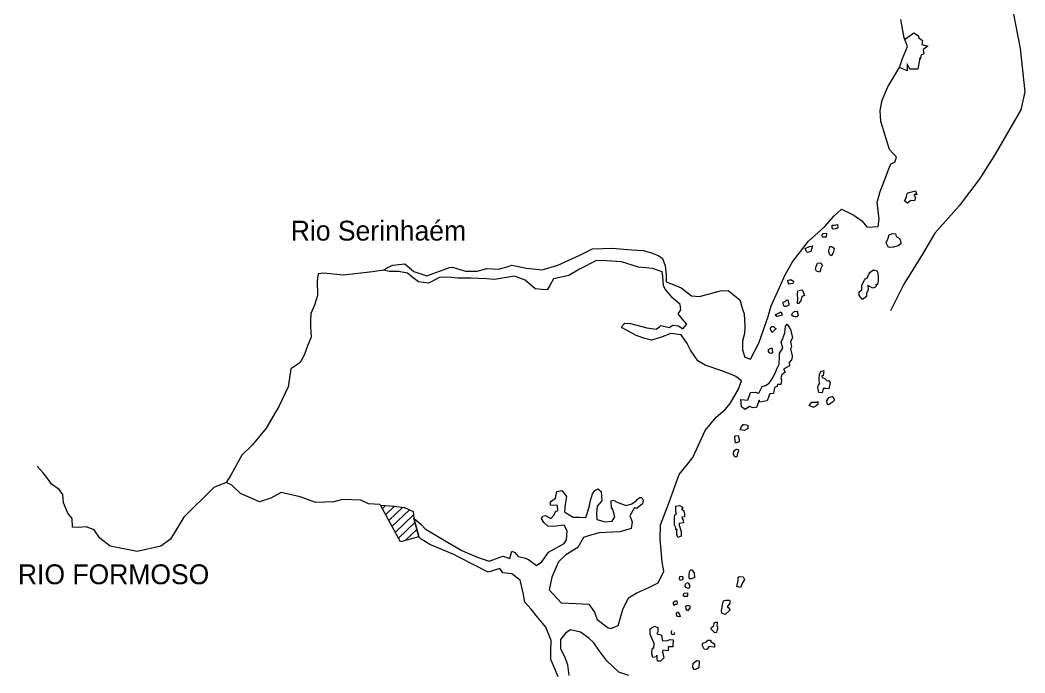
# Model space of a CAD drawing. Extents: x 662444 to 1640468, y 7452018 to 9606170.
# Drawn here: x 1574839 to 1609576, y 9023325 to 9045876 of the extents above; entities that cross this region are included whole.
import ezdxf

# ---------------------------------------------------------------- set-up
doc = ezdxf.new("R2010")
doc.units = 0
doc.layers.add('Level 1', color=7, linetype='Continuous')
doc.layers.add('Level 3', color=7, linetype='Continuous')

msp = doc.modelspace()

# ---------------------------------------------------------------- linework, layer by layer
at = {"layer": 'Level 1'}
for points in [[(1603524, 9039212), (1603667, 9039136), (1603937, 9038941), (1604118, 9038725), (1604506, 9038748), (1604537, 9038998), (1604463, 9039576), (1604578, 9039954), (1604752, 9040428), (1604847, 9040684), (1604943, 9040909), (1605074, 9040970), (1605134, 9041138), (1604899, 9041405), (1604592, 9042377), (1604577, 9042752), (1604644, 9043106), (1604834, 9043571), (1605222, 9044210), (1605239, 9044242), (1605344, 9044547), (1605517, 9044964), (1605403, 9045267), (1605290, 9045902)], [(1609180, 9046082), (1609417, 9044899), (1609576, 9043399), (1609436, 9042776), (1608544, 9041247), (1608020, 9040401), (1607300, 9039455), (1606467, 9038518), (1606041, 9037786), (1605392, 9036756), (1604931, 9035830)], [(1605403, 9045267), (1605450, 9045234), (1605739, 9045436), (1605898, 9045334), (1605896, 9045270), (1606031, 9045169), (1606012, 9045039), (1606220, 9044978), (1606055, 9044860), (1606084, 9044705), (1605995, 9044675), (1605958, 9044530), (1605943, 9044571), (1605877, 9044184), (1605602, 9044183), (1605509, 9044364), (1605503, 9044121), (1605239, 9044242)], [(1605564, 9039919), (1605662, 9039949), (1605792, 9039977), (1605837, 9039847), (1605749, 9039849), (1605748, 9039824), (1605794, 9039750), (1605759, 9039638), (1605629, 9039641), (1605514, 9039555), (1605411, 9039631), (1605487, 9039758), (1605490, 9039856), (1605523, 9039895), (1605564, 9039919)], [(1595750, 9035402), (1595936, 9035397), (1596506, 9035244), (1596829, 9035203), (1596944, 9035281), (1596994, 9035328), (1597283, 9035255), (1597406, 9035333), (1597599, 9035312), (1597751, 9035210), (1597884, 9035368), (1597727, 9035551), (1597586, 9035725), (1597678, 9035869), (1597659, 9036056), (1597399, 9036273), (1597155, 9036572), (1597086, 9036696), (1597054, 9037029), (1597041, 9037183), (1596697, 9037297), (1596213, 9037344), (1595635, 9037522), (1595126, 9037559), (1594763, 9037569), (1594173, 9037269), (1593804, 9037052), (1593284, 9036944), (1593148, 9036713), (1593055, 9036562), (1592885, 9036566), (1592643, 9036597), (1592296, 9036898), (1591927, 9037030), (1591245, 9036919), (1590963, 9036934), (1590422, 9036957), (1589976, 9036960), (1589630, 9036994), (1589339, 9036986), (1588962, 9036794), (1588607, 9036836), (1588433, 9036978), (1588235, 9037137), (1587921, 9037187), (1587598, 9037195), (1587397, 9037233), (1587545, 9037326), (1587725, 9037410), (1588138, 9037456), (1588455, 9037196), (1588896, 9037047), (1589688, 9037325), (1589784, 9037347), (1590234, 9037205), (1590646, 9037202), (1590980, 9037298), (1591375, 9037271), (1591709, 9037368), (1591840, 9037413), (1592347, 9037310), (1592887, 9037247), (1593424, 9037411), (1594194, 9037754), (1594628, 9037978), (1595316, 9038000), (1595977, 9037941), (1596389, 9037914), (1596702, 9037825), (1596926, 9037729), (1597046, 9037645), (1597144, 9037383), (1597176, 9037082), (1597170, 9036830), (1597530, 9036700), (1597698, 9036630), (1598048, 9036353), (1598330, 9036329), (1598753, 9036448), (1599054, 9036529), (1599321, 9036530), (1599718, 9036218), (1599814, 9035891), (1599875, 9035728), (1599896, 9035298), (1599881, 9035047), (1599818, 9034789), (1599810, 9034489), (1599892, 9034236), (1600085, 9034166), (1600382, 9034717), (1600706, 9035632), (1600804, 9036002), (1601095, 9036644), (1601284, 9037076), (1601539, 9037531), (1602099, 9038237), (1602645, 9038734), (1602979, 9039113), (1603236, 9039350), (1603524, 9039212)], [(1602721, 9038513), (1602709, 9038375), (1602645, 9038377), (1602580, 9038378), (1602565, 9038444), (1602599, 9038499), (1602721, 9038513)], [(1602986, 9038789), (1603092, 9038811), (1603114, 9038705), (1603048, 9038666), (1602950, 9038652), (1602911, 9038702), (1602913, 9038758), (1602914, 9038791), (1602978, 9038789)], [(1605021, 9038028), (1604899, 9038023), (1604844, 9038041), (1604783, 9038180), (1604852, 9038341), (1604887, 9038454), (1604985, 9038499), (1605099, 9038496), (1605129, 9038406), (1605224, 9038339), (1605278, 9038264), (1605284, 9038150), (1605193, 9038080), (1605021, 9038028)], [(1602135, 9038058), (1602232, 9038080), (1602170, 9037887), (1602064, 9037850), (1602025, 9037883), (1601980, 9037981), (1602135, 9038058)], [(1602963, 9037865), (1602887, 9037737), (1602831, 9037763), (1602793, 9037862), (1602795, 9037918), (1602831, 9038055), (1602894, 9038054), (1602982, 9038003), (1602963, 9037865)], [(1602571, 9037382), (1602519, 9037293), (1602491, 9037165), (1602372, 9037208), (1602333, 9037275), (1602359, 9037363), (1602411, 9037484), (1602509, 9037489), (1602556, 9037446), (1602571, 9037382)], [(1587397, 9037233), (1587023, 9037178), (1586018, 9037060), (1585324, 9037135), (1585138, 9037115), (1585107, 9036864), (1585119, 9036362), (1585022, 9036024), (1584885, 9035736), (1584878, 9035477), (1584874, 9035290), (1584904, 9034925), (1584776, 9034621), (1584655, 9034300), (1584511, 9034036), (1584198, 9033834), (1584109, 9033204), (1583801, 9032548), (1583345, 9031782), (1582861, 9031195), (1582505, 9030849), (1582123, 9030154), (1581963, 9029899)], [(1604146, 9036706), (1604145, 9036674), (1604159, 9036600), (1604141, 9036520), (1604099, 9036448), (1604096, 9036326), (1603956, 9036225), (1603846, 9036366), (1603841, 9036487), (1603940, 9036558), (1603944, 9036719), (1604029, 9036895), (1604063, 9036943), (1604128, 9036958), (1604164, 9037078), (1604222, 9037174), (1604346, 9037252), (1604458, 9037217), (1604489, 9037143), (1604501, 9036996), (1604499, 9036899), (1604498, 9036866), (1604478, 9036738), (1604445, 9036722), (1604430, 9036755), (1604429, 9036690), (1604387, 9036642), (1604322, 9036612), (1604146, 9036706)], [(1601586, 9036849), (1601551, 9036776), (1601421, 9036756), (1601390, 9036813), (1601376, 9036879), (1601442, 9036902), (1601506, 9036900), (1601586, 9036849)], [(1601764, 9036536), (1601870, 9036557), (1601901, 9036524), (1601924, 9036442), (1601953, 9036361), (1601864, 9036330), (1601827, 9036178), (1601752, 9036082), (1601720, 9036083), (1601725, 9036269), (1601710, 9036359), (1601711, 9036392), (1601731, 9036520)], [(1601383, 9036197), (1601413, 9036091), (1601419, 9036027), (1601320, 9035980), (1601256, 9035982), (1601218, 9036072), (1601219, 9036137), (1601285, 9036151), (1601351, 9036215), (1601383, 9036197)], [(1601184, 9035684), (1601061, 9035646), (1600996, 9035640), (1600950, 9035707), (1600983, 9035721), (1601080, 9035768), (1601113, 9035791), (1601146, 9035798), (1601184, 9035684)], [(1601583, 9035794), (1601615, 9035810), (1601696, 9035824), (1601712, 9035783), (1601711, 9035751), (1601741, 9035669), (1601692, 9035630), (1601635, 9035631), (1601571, 9035641), (1601507, 9035683), (1601557, 9035763), (1601583, 9035794)], [(1593007, 9028765), (1593190, 9028663), (1593307, 9028781), (1593343, 9028901), (1593432, 9028931), (1593421, 9029110), (1593170, 9029116), (1593173, 9029239), (1593346, 9029363), (1593392, 9029589), (1593572, 9029624), (1593728, 9029418), (1593680, 9029144), (1593657, 9028893), (1593761, 9028825), (1593960, 9028706), (1594162, 9028701), (1594396, 9028695), (1594518, 9029047), (1594557, 9029282), (1594627, 9029507), (1594711, 9029626), (1594810, 9029681), (1594929, 9029596), (1594953, 9029271), (1594794, 9029088), (1594764, 9028830), (1594782, 9028627), (1595063, 9028538), (1595306, 9028564), (1595399, 9028716), (1595333, 9028969), (1595279, 9029043), (1595276, 9029270), (1595358, 9029292), (1595501, 9029216), (1595790, 9029111), (1595984, 9029162), (1596132, 9029271), (1596199, 9029334), (1596265, 9029381), (1596330, 9029379), (1596377, 9029297), (1596357, 9029167), (1596167, 9029019), (1596070, 9029021), (1595918, 9028750), (1596001, 9028545), (1595962, 9028319), (1595571, 9028193), (1594843, 9028163), (1594492, 9028059), (1594321, 9028000), (1594126, 9027656), (1593700, 9027408), (1593451, 9027164), (1593227, 9026627), (1593126, 9026199), (1593543, 9025743), (1594068, 9025728), (1594496, 9025700), (1594691, 9025420), (1594789, 9025166), (1595170, 9024880), (1595258, 9024860), (1595520, 9024967), (1595679, 9025514), (1595868, 9025922), (1596155, 9026093), (1596572, 9026276), (1596892, 9026437), (1597096, 9026845), (1597040, 9027163), (1596972, 9027943), (1596984, 9028437), (1597271, 9029192), (1597629, 9030179), (1598096, 9030766), (1598517, 9031702), (1598900, 9032155), (1599215, 9032429), (1599382, 9032636), (1599678, 9033122), (1599774, 9033412), (1599584, 9033562), (1599456, 9033623), (1599096, 9033755), (1598519, 9033956), (1598271, 9034110), (1598015, 9034474), (1597899, 9034703), (1597697, 9035008), (1597334, 9035052), (1596983, 9034915), (1596665, 9034825), (1596440, 9034881), (1596136, 9034986), (1595952, 9035089), (1595649, 9035243), (1595634, 9035276), (1595750, 9035402)], [(1601232, 9033818), (1601287, 9033719), (1601178, 9033617), (1601144, 9033520), (1601158, 9033439), (1601138, 9033286), (1601024, 9033289), (1601014, 9033224), (1600924, 9033186), (1600887, 9032976), (1600758, 9032971), (1600723, 9032884), (1600662, 9032723), (1600410, 9032681), (1600387, 9032747), (1600293, 9032498), (1600178, 9032485), (1600059, 9032529), (1599910, 9032419), (1599783, 9032511), (1599758, 9032772), (1600000, 9032741), (1600095, 9033014), (1600250, 9033026), (1600378, 9032990), (1600497, 9033222), (1600611, 9033259), (1600735, 9033329), (1600844, 9033488), (1600894, 9033584), (1600963, 9033736), (1601014, 9033856), (1601075, 9033985), (1601089, 9034244), (1601092, 9034365), (1601202, 9034540), (1601152, 9034753), (1601219, 9034897), (1601229, 9034945), (1601281, 9035074), (1601295, 9035308), (1601361, 9035371), (1601447, 9035223), (1601470, 9035198), (1601544, 9034904), (1601475, 9034776), (1601511, 9034588), (1601469, 9034517), (1601535, 9034280), (1601525, 9034215), (1601508, 9034135), (1601424, 9034047), (1601438, 9033934), (1601331, 9033872), (1601232, 9033818)], [(1600977, 9035220), (1600844, 9035085), (1600782, 9035185), (1600784, 9035241), (1600825, 9035289), (1600857, 9035287), (1600890, 9035286), (1600938, 9035229), (1600977, 9035220)], [(1600822, 9034550), (1600838, 9034517), (1600850, 9034380), (1600818, 9034364), (1600753, 9034366), (1600707, 9034432), (1600708, 9034497), (1600822, 9034550)], [(1602742, 9033420), (1602798, 9033426), (1602846, 9033352), (1602827, 9033296), (1602800, 9033142), (1602678, 9033145), (1602606, 9033148), (1602562, 9033004), (1602457, 9033006), (1602420, 9033186), (1602431, 9033250), (1602472, 9033306), (1602469, 9033477), (1602473, 9033630), (1602524, 9033742), (1602622, 9033772), (1602600, 9033586), (1602552, 9033588), (1602567, 9033530), (1602672, 9033487), (1602742, 9033420)], [(1602205, 9032673), (1602303, 9032678), (1602383, 9032676), (1602416, 9032699), (1602414, 9032602), (1602363, 9032554), (1602281, 9032500), (1602249, 9032501), (1602185, 9032528), (1602121, 9032561), (1602205, 9032673)], [(1602917, 9032661), (1602785, 9032591), (1602753, 9032592), (1602724, 9032723), (1602792, 9032843), (1602913, 9032872), (1602938, 9032871), (1602983, 9032773), (1602983, 9032740), (1602917, 9032661)], [(1599966, 9031744), (1599883, 9031698), (1599738, 9031726), (1599765, 9031814), (1599840, 9031902), (1599872, 9031901), (1599937, 9031900), (1599992, 9031866), (1599998, 9031752), (1599966, 9031744)], [(1599606, 9031276), (1599573, 9031277), (1599545, 9031440), (1599547, 9031505), (1599580, 9031520), (1599660, 9031525), (1599697, 9031403), (1599703, 9031305), (1599638, 9031283), (1599606, 9031276)], [(1599644, 9030918), (1599616, 9030789), (1599553, 9030791), (1599506, 9030874), (1599509, 9030995), (1599567, 9031034), (1599600, 9031049), (1599665, 9031047), (1599678, 9030983), (1599644, 9030918)], [(1587293, 9029114), (1587278, 9029147), (1586882, 9029167), (1586619, 9029295), (1585989, 9029320), (1585680, 9029232), (1585065, 9029215), (1584521, 9029409), (1583869, 9029556), (1583509, 9029363), (1583117, 9029235), (1582463, 9029528), (1582154, 9029805), (1581963, 9029899), (1581538, 9029732), (1580502, 9028706), (1580038, 9027949), (1579700, 9027707), (1578888, 9027519), (1577955, 9027705), (1577598, 9027975), (1577396, 9028272), (1577124, 9028368), (1576864, 9028351), (1576655, 9028356), (1576638, 9028656), (1576490, 9028847), (1576337, 9029199), (1576320, 9029491), (1576195, 9029657), (1575925, 9029850), (1575800, 9030032), (1575636, 9030239), (1575424, 9030463)], [(1588623, 9028025), (1587988, 9027847), (1587293, 9029114), (1587769, 9029085), (1588124, 9029043), (1588427, 9028897), (1588454, 9028670), (1588623, 9028025)], [(1587360, 9028992), (1587476, 9029103)], [(1597522, 9028309), (1597461, 9028432), (1597467, 9028684), (1597470, 9028789), (1597536, 9028811), (1597505, 9028877), (1597503, 9029080), (1597633, 9029108), (1597736, 9029049), (1597735, 9028992), (1597702, 9028977), (1597766, 9028943), (1597781, 9028910), (1597810, 9028812), (1597808, 9028715), (1597711, 9028709), (1597726, 9028660), (1597765, 9028603), (1597770, 9028513), (1597624, 9028484), (1597623, 9028428), (1597698, 9028207), (1597694, 9028045), (1597579, 9028007), (1597542, 9028106), (1597544, 9028203), (1597554, 9028276), (1597489, 9028278), (1597522, 9028309)], [(1587471, 9028790), (1587780, 9029084)], [(1587583, 9028586), (1588068, 9029050)], [(1587694, 9028383), (1588298, 9028959)], [(1587806, 9028180), (1588440, 9028786)], [(1593445, 9023192), (1593337, 9023437), (1593185, 9023791), (1593192, 9024082), (1593202, 9024439), (1593012, 9024906), (1592729, 9025246), (1592511, 9025528), (1592283, 9025769), (1592227, 9026086), (1592124, 9026527), (1591840, 9026745), (1591525, 9026778), (1591423, 9026928), (1591016, 9026800), (1590011, 9027323), (1589836, 9027416), (1589004, 9027755), (1588702, 9027950), (1588623, 9028025), (1588454, 9028670), (1588699, 9028452), (1588848, 9028303), (1589620, 9027836), (1590114, 9027555), (1590299, 9027477), (1590706, 9027303), (1591051, 9027189), (1591532, 9027361), (1591764, 9027282), (1591844, 9027532), (1591947, 9027489), (1592057, 9027348), (1592266, 9027302), (1592418, 9027241), (1592553, 9027139), (1592687, 9027038), (1592877, 9027163), (1593111, 9027497), (1593645, 9027799), (1593729, 9027927), (1593754, 9028234), (1593645, 9028431), (1593272, 9028384), (1593087, 9028389), (1592944, 9028523), (1592867, 9028663), (1592909, 9028735), (1593007, 9028765)], [(1587916, 9027977), (1588491, 9028525)], [(1588153, 9027893), (1588556, 9028278)], [(1588612, 9028022), (1588621, 9028031)], [(1597694, 9026529), (1597662, 9026521), (1597640, 9026587), (1597642, 9026652), (1597673, 9026659), (1597738, 9026665), (1597753, 9026584), (1597752, 9026551), (1597694, 9026529)], [(1597975, 9026732), (1597992, 9026851), (1598028, 9026884), (1598060, 9026883), (1598138, 9026785), (1598150, 9026622), (1598052, 9026576), (1597987, 9026570), (1597971, 9026603), (1597973, 9026667), (1597975, 9026732)], [(1597836, 9026338), (1597842, 9026394), (1597873, 9026429), (1597935, 9026449), (1597951, 9026416), (1597981, 9026351), (1597979, 9026278), (1597946, 9026239), (1597857, 9026273), (1597836, 9026338)], [(1599659, 9026515), (1599661, 9026613), (1599695, 9026653), (1599832, 9026649), (1599878, 9026550), (1599845, 9026494), (1599811, 9026431), (1599742, 9026270), (1599621, 9026305), (1599659, 9026515)], [(1597910, 9026094), (1597907, 9025996), (1597891, 9025964), (1597793, 9025959), (1597769, 9025984), (1597771, 9026048), (1597812, 9026079), (1597910, 9026094)], [(1597473, 9025805), (1597506, 9025820), (1597538, 9025819), (1597553, 9025754), (1597544, 9025690), (1597511, 9025682), (1597479, 9025683), (1597453, 9025643), (1597423, 9025709), (1597424, 9025774), (1597473, 9025805)], [(1597910, 9025469), (1597862, 9025535), (1597857, 9025632), (1597890, 9025656), (1597955, 9025655), (1597987, 9025629), (1597993, 9025564), (1597910, 9025469)], [(1599287, 9025609), (1599319, 9025584), (1599390, 9025501), (1599216, 9025344), (1599104, 9025387), (1599090, 9025485), (1599109, 9025581), (1599138, 9025743), (1599172, 9025831), (1599237, 9025837), (1599301, 9025836), (1599366, 9025834), (1599373, 9025801), (1599380, 9025737), (1599287, 9025609)], [(1597639, 9025339), (1597662, 9025273), (1597630, 9025266), (1597565, 9025275), (1597541, 9025309), (1597526, 9025374), (1597560, 9025429), (1597593, 9025428), (1597601, 9025397), (1597639, 9025339)], [(1596752, 9024171), (1596764, 9024341), (1596665, 9024546), (1596620, 9024662), (1596623, 9024848), (1596763, 9024941), (1596884, 9024897), (1596888, 9024743), (1596854, 9024679), (1596942, 9024652), (1597014, 9024634), (1597035, 9024479), (1597042, 9024447), (1597186, 9024427), (1597310, 9024480), (1597414, 9024469), (1597408, 9024226), (1597246, 9024231), (1597244, 9024149), (1597242, 9024085), (1597058, 9024114), (1597048, 9024050), (1597091, 9023846), (1596975, 9023727), (1596878, 9023730), (1596851, 9023942), (1596849, 9023877), (1596711, 9023856), (1596674, 9023979), (1596695, 9024157), (1596728, 9024196), (1596752, 9024171)], [(1598826, 9024957), (1598836, 9025054), (1598919, 9025093), (1598933, 9025060), (1598931, 9024962), (1598946, 9024905), (1598952, 9024840), (1598926, 9024793), (1598917, 9024720), (1598852, 9024714), (1598734, 9024830), (1598736, 9024895), (1598826, 9024957)], [(1595886, 9023239), (1595534, 9023354), (1595123, 9023746), (1594850, 9024110), (1594671, 9024366), (1594497, 9024525), (1594212, 9024728), (1593866, 9024817), (1593703, 9024708), (1593527, 9024478), (1593518, 9024154), (1593673, 9023866), (1593763, 9023605), (1593809, 9023231)], [(1597453, 9024719), (1597452, 9024654), (1597386, 9024640), (1597363, 9024697), (1597364, 9024730), (1597366, 9024795)], [(1598654, 9024241), (1598620, 9024177), (1598578, 9024137), (1598489, 9024140), (1598427, 9024255), (1598429, 9024320), (1598470, 9024359), (1598553, 9024389), (1598619, 9024452), (1598700, 9024458), (1598730, 9024400), (1598849, 9024332), (1598847, 9024219), (1598823, 9024219), (1598654, 9024241)], [(1598236, 9023749), (1598317, 9023747), (1598302, 9023496), (1598213, 9023450), (1598148, 9023436), (1598101, 9023526), (1598104, 9023656), (1598236, 9023749)]]:
    msp.add_lwpolyline(points, dxfattribs=at)

# ---------------------------------------------------------------- texts
at = {"layer": 'Level 3'}
for s, height, p in [('Rio Serinhaém', 685.36, (1584196, 9038260)), ('RIO FORMOSO', 684.98, (1574764, 9026389))]:
    msp.add_text(s, height=height, dxfattribs=at).set_placement(p)

doc.saveas('drawing.dxf')
